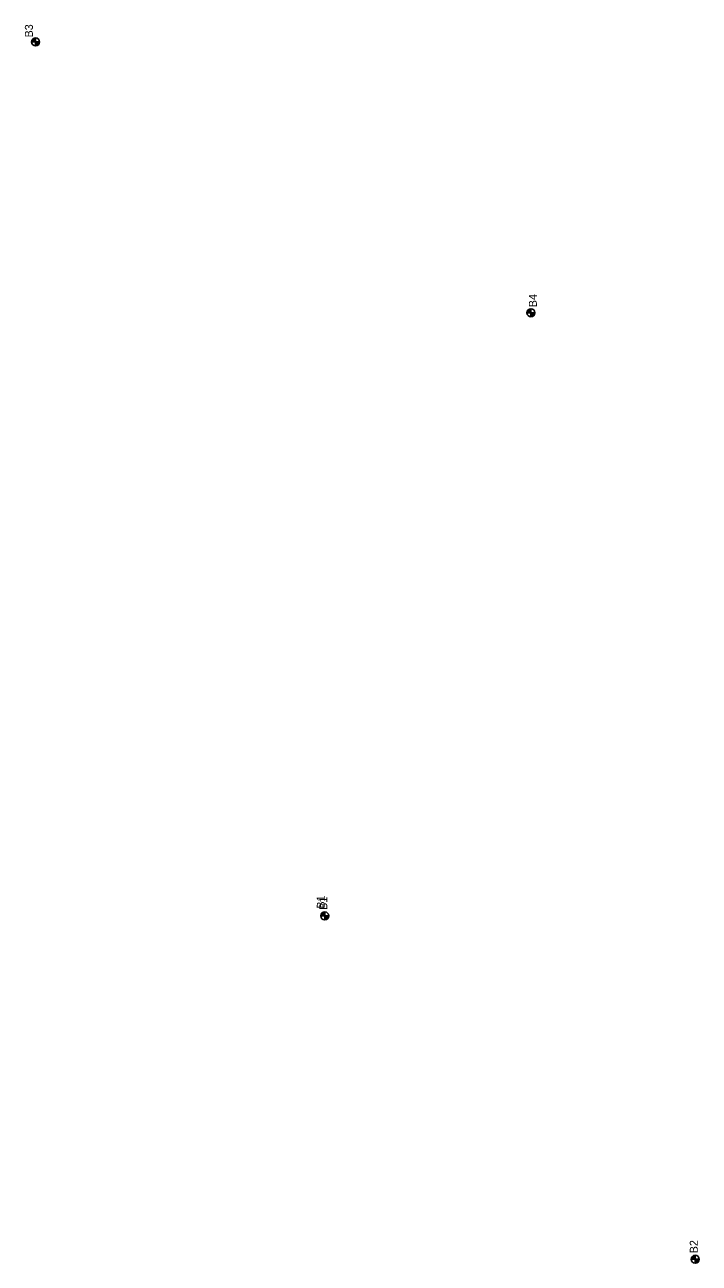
# Model space of a CAD drawing. Extents: x 327762 to 372792, y 127949 to 259367.
# Drawn here: x 361361 to 362205, y 127949 to 129496 of the extents above; entities that cross this region are included whole.
import ezdxf

# ---------------------------------------------------------------- set-up
doc = ezdxf.new("R2010")
doc.units = 0
for name, color, linetype in [('E_SOIL_BORE1 [KAPUR_CADDS_LEVELS]', 7, 'Continuous'), ('E_SOIL_BORE2 [KAPUR_CADDS_LEVELS]', 7, 'Continuous'), ('P_MARK', 7, 'Continuous')]:
    doc.layers.add(name, color=color, linetype=linetype)

msp = doc.modelspace()

# ---------------------------------------------------------------- linework, layer by layer
at = {"layer": 'P_MARK'}
for p, q in [((361369.9, 129475), (361379.9, 129475)), ((361374.9, 129480), (361374.9, 129470)), ((361989.2, 129136.5), (361999.2, 129136.5)), ((361994.2, 129141.5), (361994.2, 129131.5)), ((361736.5, 128387.8), (361736.5, 128377.8)), ((361731.5, 128382.8), (361741.5, 128382.8)), ((362194.6, 127953.7), (362204.6, 127953.7)), ((362199.6, 127958.7), (362199.6, 127948.7))]:
    msp.add_line(p, q, dxfattribs=at)
for centre in [(361374.9, 129475), (361994.2, 129136.5), (361736.5, 128382.8), (362199.6, 127953.7)]:
    msp.add_circle(centre, 5, dxfattribs=at)
for centre, radius, start, end in [((361374.9, 129475), 4.5, 89.9869, 179.9869), ((361374.9, 129475), 4, 89.9869, 179.9869), ((361374.9, 129475), 3.5, 89.9869, 179.9869), ((361374.9, 129475), 3, 89.9869, 179.9869), ((361374.9, 129475), 2.5, 89.9869, 179.9869), ((361374.9, 129475), 2, 89.9869, 179.9869), ((361374.9, 129475), 1.5, 89.9869, 179.9869), ((361374.9, 129475), 1, 89.9869, 179.9869), ((361374.9, 129475), 0.5, 89.9869, 179.9869), ((361374.9, 129475), 4.5, 269.9869, 359.9869), ((361374.9, 129475), 4, 269.9869, 359.9869), ((361374.9, 129475), 3.5, 269.9869, 359.9869), ((361374.9, 129475), 3, 269.9869, 359.9869), ((361374.9, 129475), 2.5, 269.9869, 359.9869), ((361374.9, 129475), 2, 269.9869, 359.9869), ((361374.9, 129475), 1.5, 269.9869, 359.9869), ((361374.9, 129475), 1, 269.9869, 359.9869), ((361374.9, 129475), 0.5, 269.9869, 359.9869), ((361994.2, 129136.5), 4.5, 89.9869, 179.9869), ((361994.2, 129136.5), 4, 89.9869, 179.9869), ((361994.2, 129136.5), 3.5, 89.9869, 179.9869), ((361994.2, 129136.5), 3, 89.9869, 179.9869), ((361994.2, 129136.5), 2.5, 89.9869, 179.9869), ((361994.2, 129136.5), 2, 89.9869, 179.9869), ((361994.2, 129136.5), 1.5, 89.9869, 179.9869), ((361994.2, 129136.5), 1, 89.9869, 179.9869), ((361994.2, 129136.5), 0.5, 89.9869, 179.9869), ((361994.2, 129136.5), 4.5, 269.9869, 359.9869), ((361994.2, 129136.5), 4, 269.9869, 359.9869), ((361994.2, 129136.5), 3.5, 269.9869, 359.9869), ((361994.2, 129136.5), 3, 269.9869, 359.9869), ((361994.2, 129136.5), 2.5, 269.9869, 359.9869), ((361994.2, 129136.5), 2, 269.9869, 359.9869), ((361994.2, 129136.5), 1.5, 269.9869, 359.9869), ((361994.2, 129136.5), 1, 269.9869, 359.9869), ((361994.2, 129136.5), 0.5, 269.9869, 359.9869), ((361736.5, 128382.8), 4.5, 89.9869, 179.9869), ((361736.5, 128382.8), 4, 89.9869, 179.9869), ((361736.5, 128382.8), 3.5, 89.9869, 179.9869), ((361736.5, 128382.8), 3, 89.9869, 179.9869), ((361736.5, 128382.8), 2.5, 89.9869, 179.9869), ((361736.5, 128382.8), 2, 89.9869, 179.9869), ((361736.5, 128382.8), 1.5, 89.9869, 179.9869), ((361736.5, 128382.8), 1, 89.9869, 179.9869), ((361736.5, 128382.8), 0.5, 89.9869, 179.9869), ((361736.5, 128382.8), 4.5, 269.9869, 359.9869), ((361736.5, 128382.8), 4, 269.9869, 359.9869), ((361736.5, 128382.8), 3.5, 269.9869, 359.9869), ((361736.5, 128382.8), 3, 269.9869, 359.9869), ((361736.5, 128382.8), 2.5, 269.9869, 359.9869), ((361736.5, 128382.8), 2, 269.9869, 359.9869), ((361736.5, 128382.8), 1.5, 269.9869, 359.9869), ((361736.5, 128382.8), 1, 269.9869, 359.9869), ((361736.5, 128382.8), 0.5, 269.9869, 359.9869), ((362199.6, 127953.7), 4.5, 89.9869, 179.9869), ((362199.6, 127953.7), 4, 89.9869, 179.9869), ((362199.6, 127953.7), 3.5, 89.9869, 179.9869), ((362199.6, 127953.7), 3, 89.9869, 179.9869), ((362199.6, 127953.7), 2.5, 89.9869, 179.9869), ((362199.6, 127953.7), 2, 89.9869, 179.9869), ((362199.6, 127953.7), 1.5, 89.9869, 179.9869), ((362199.6, 127953.7), 1, 89.9869, 179.9869), ((362199.6, 127953.7), 0.5, 89.9869, 179.9869), ((362199.6, 127953.7), 4.5, 269.9869, 359.9869), ((362199.6, 127953.7), 4, 269.9869, 359.9869), ((362199.6, 127953.7), 3.5, 269.9869, 359.9869), ((362199.6, 127953.7), 3, 269.9869, 359.9869), ((362199.6, 127953.7), 2.5, 269.9869, 359.9869), ((362199.6, 127953.7), 2, 269.9869, 359.9869), ((362199.6, 127953.7), 1.5, 269.9869, 359.9869), ((362199.6, 127953.7), 1, 269.9869, 359.9869), ((362199.6, 127953.7), 0.5, 269.9869, 359.9869)]:
    msp.add_arc(centre, radius, start, end, dxfattribs=at)

# ---------------------------------------------------------------- texts
at = {"layer": 'E_SOIL_BORE1 [KAPUR_CADDS_LEVELS]'}
for s, p in [('B3', (361371.5, 129480.7)), ('B4', (362001.6, 129143.5)), ('B1', (361736.5, 128391.9))]:
    msp.add_text(s, height=10, rotation=89.9869, dxfattribs=at).set_placement(p)
at = {"layer": 'E_SOIL_BORE2 [KAPUR_CADDS_LEVELS]'}
for s, p in [('B1', (361739.6, 128390.3)), ('B2', (362202.8, 127961.2))]:
    msp.add_text(s, height=10, rotation=89.9869, dxfattribs=at).set_placement(p)

doc.saveas('drawing.dxf')
